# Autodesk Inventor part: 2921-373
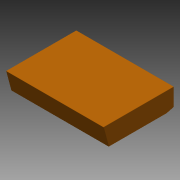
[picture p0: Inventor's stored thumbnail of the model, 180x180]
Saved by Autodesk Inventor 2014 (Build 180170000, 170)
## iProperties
Company: nhtsa/vrtc
Created: 2012-02
Part Number: 2921-373
Project: CHILD SID IMPACT SLED
Material: Generic
Description: BOTTOM SEAT CUSHION COVER
Document SubType Name: Modeling
Designer: Mike Vanvoorhis
Density: 1 g/cm^3
Mass: 747.29 g
Surface Area: 18755.2 cm^2
Volume: 747.29 cm^3
Appearance: Orange
Title: Bottom Seat Cushion Cover
Subject: Child Side Impact Sled
Author: Dave Walker
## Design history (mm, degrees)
sketch "Sketch1"
  geometry: L1 (347.5, 250)-(347.5, -250); L2 (347.5, -250)-(-347.5, -250); L3 (-347.5, -250)-(-347.5, 250); L4 (-486.5, 0)-(486.5, 0) reference; L5 (0, 350)-(0, -350) reference; L6 (-347.5, 250)-(347.5, 250); 1 further point
  constraints: 8 end point, 2 parallel, 1 horizontal, 1 midpoint, 1 perpendicular, 1 point on line, 2 other
  dimensions: "d0" = 695 distance of L3.end L1.start; "d1" = 500 distance of L2.end L3.end
extrude "Extrusion1" new body sketch "Sketch1" distance "d7" = 0.79375; taper "d8" = 0 deg
sketch "Sketch10"
  geometry: L1 (0, 0)-(0, 500) reference; L2 (0.794, 0)-(0.794, 500) reference; L3 (0.794, 0)-(139, 37.032); L4 (139, 37.032)-(139, 450); L5 (0, 500)-(125.603, 500); L6 (125.603, 500)-(139, 450); L7 (0.794, 0)-(0, 0); L8 (0, 0.048)-(0, 500); 1 further point
  constraints: 12 end point, 2 parallel, 2 perpendicular, 1 horizontal, 1 point on line
  dimensions: "d67" = 75 deg angle of L3 L2; "d128" = 139 distance between parallel lines of L4 L1; "d129" = 50 distance from line of L4.end L5; "d130" = 15 deg angle of L6 L4
extrude "Extrusion7" join sketch "Sketch10" distance "d70" = 0.8; taper "d71" = 0 deg
mirror "Mirror5"
sketch "Sketch11"
  geometry: L1 (-0.8, 143.848)-(695.8, 143.848) reference; L2 (-0.8, 0)-(-0.8, 143.082) reference; L3 (695.8, 0)-(695.8, 143.082) reference; L4 (695.8, 0)-(-0.8, 0); L5 (-0.8, 0)-(-0.8, 143.848); L6 (-0.8, 143.848)-(695.8, 143.848); L7 (695.8, 143.848)-(695.8, 0); 1 further point
  constraints: 8 end point, 2 collinear, 2 perpendicular
extrude "Extrusion8" join sketch "Sketch11" distance "d72" = 0.8; taper "d73" = 0 deg
sketch "Sketch12"
  geometry: L1 (0.794, 0)-(0, 0) reference; L2 (0.794, 0)-(0.053, -0.198) reference; L3 (0, 0)-(0.053, -0.198); 1 further point
  constraints: 2 end point, 1 perpendicular
extrude "Extrusion9" join sketch "Sketch12" stored distance "d74" = 0.8; taper "d75" = 0 deg
sketch "Sketch13"
  geometry: L1 (139, 37.032)-(139.207, 36.26) reference; L2 (0.26, -0.971)-(139.207, 36.26) reference; L3 (139, 450)-(139, 37.032) reference; L4 (139, 37.032)-(139, 36.204); 1 further point
  constraints: 2 end point, 1 collinear, 1 point on line
extrude "Extrusion10" cut sketch "Sketch13" stored distance "d76" = 0.8; taper "d77" = 0 deg
sketch "Sketch14"
  geometry: L1 (-695.8, -0.828)-(-695.8, 412.968) reference; L2 (0.8, -0.828)-(-695.8, -0.828) reference; L3 (0.8, 412.968)-(0.8, -0.828) reference; L4 (0.8, 412.968)-(-695.8, 412.968); 1 further point
  constraints: 2 end point, 1 perpendicular
extrude "Extrusion11" join sketch "Sketch14" distance "d78" = 0.8; taper "d79" = 0 deg
sketch "Sketch17"
  geometry: L1 (0.8, 51.764)-(0.8, 0) reference; L2 (-695, 0)-(0, 0) reference; L3 (0.8, 51.764)-(-695.8, 51.764); L4 (-695.8, 51.764)-(-695.8, 0); L5 (-695.8, 0)-(0.8, 0); L6 (0.8, 0)-(0.8, 51.764); L7 (-695.8, 51.764)-(-695.8, 0) reference; 2 further points
  constraints: 8 end point, 2 collinear, 2 parallel, 1 horizontal, 1 perpendicular
extrude "Extrusion14" join sketch "Sketch17" distance "d86" = 0.8; taper "d87" = 0 deg
sketch "Sketch18"
  geometry: L1 (-139, 450)-(-139.773, 450.207) reference; L2 (-139, 450)-(-139.8, 450) reference; L3 (-126.375, 500.207)-(-139.773, 450.207) reference; L4 (-139.773, 450.207)-(-139.8, 450); 1 further point
  constraints: 2 end point
extrude "Extrusion15" join sketch "Sketch18" stored distance "d88" = 0.8; taper "d89" = 0 deg
sketch "Sketch27"
  geometry: L1 (139.8, 36.204)-(139.8, 450) reference; L2 (139.773, 450.207)-(126.375, 500.207) reference; L3 (125.603, 500)-(126.375, 500.207) reference; L4 (125.603, 500)-(126.431, 500); L5 (126.431, 500)-(126.375, 500.207); L6 (126.375, 500.207)-(125.603, 500); 1 further point
  constraints: 6 end point, 2 perpendicular, 1 collinear, 1 point on line
extrude "Extrusion21" cut sketch "Sketch27" stored distance "d156" = 0; taper "d157" = 0 deg
sketch "Sketch28"
  geometry: L1 (0, 0)-(696.6, 0); L2 (696.6, 0)-(696.6, 126.431); L3 (696.6, 126.431)-(0, 126.431); L4 (0, 126.431)-(0, 0); 1 further point
  constraints: 8 end point, 2 parallel, 1 horizontal, 1 perpendicular
extrude "Extrusion22" join sketch "Sketch28" distance "d158" = 1; taper "d159" = 0 deg
sketch "Sketch29"
  geometry: L1 (139.773, 450.207)-(126.431, 500) reference; L2 (126.431, 500)-(126.431, 501) reference; L3 (0, 501)-(126.431, 501) reference; L4 (126.431, 500)-(126.163, 501); L5 (126.163, 501)-(126.431, 501); L6 (126.431, 500)-(126.431, 501); 1 further point
  constraints: 6 end point, 3 collinear, 1 point on line
extrude "Extrusion23" cut sketch "Sketch29" stored distance "d160" = 2; taper "d161" = 0 deg
sketch "Sketch23"
  geometry: L1 (0, 0)-(-695, 0) reference; 6 further points; 1 other entity
  constraints: 2 horizontal alignment, 1 other
  dimensions: "d112" = 55 dimension on point (-640, 74); "d113" = 348.3 dimension on point (-346.7, 74); "d114" = 640 dimension on point (-55, 74); "d115" = 74 distance from line of point (-640, 74) L1
hole "Hole4" sketch "Sketch23" at (-640, 74), (-346.7, 74), (-55, 74) diameter "d118" = 9.5; stored, may be unused: countersink angle "d122" = 90 deg, drill point angle "d124" = 118 deg; dims "d119" = 6, "d120" = 4, "d121" = 2, "d123" = 8
sketch "Sketch30"
  geometry: L1 (-695.8, 52.585)-(0.8, 52.585) reference; 7 further points; 3 other entities
  constraints: 3 vertical alignment, 2 horizontal alignment, 3 other
  dimensions: "d164" = 10 distance from line of point (-640, 42.585) L1
hole "Hole6" sketch "Sketch30" at (-640, 42.585), (-346.7, 42.585), (-55, 42.585) diameter "d165" = 9.5; stored, may be unused: countersink angle "d169" = 90 deg, drill point angle "d171" = 0 deg; dims "d166" = 6, "d167" = 4, "d168" = 2, "d170" = 2
fillet "Fillet1" dims "d95" = 1.2
fillet "Fillet7" dims "d103" = 2
fillet "Fillet9" dims "d105" = 2
fillet "Fillet10" dims "d106" = 2
fillet "Fillet12" dims "d108" = 2
fillet "Fillet14" dims "d147" = 2
fillet "Fillet15" dims "d148" = 2
fillet "Fillet16" dims "d149" = 2
fillet "Fillet20" dims "d162" = 2
fillet "Fillet21" dims "d163" = 1
body "Solid1"
